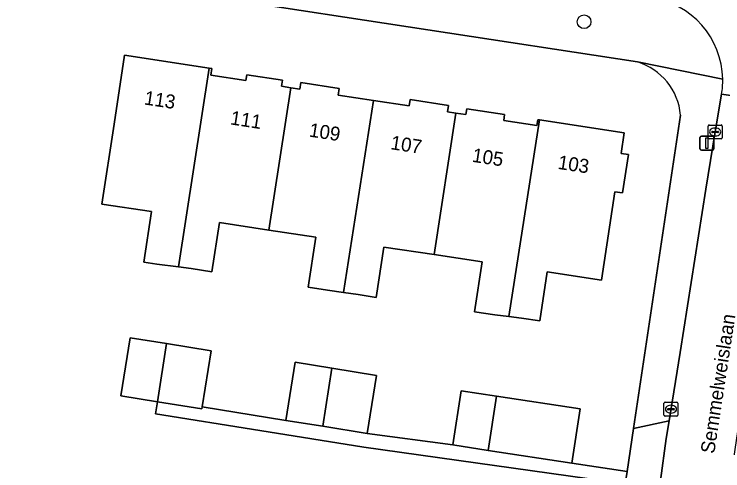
# Model space of a CAD drawing. Extents: x 161483 to 162250, y 379484 to 380833.
# Drawn here: x 161701.8 to 161752.7, y 380536.5 to 380569.3 of the extents above; entities that cross this region are included whole.
import ezdxf

# ---------------------------------------------------------------- set-up
doc = ezdxf.new("R2010")
doc.units = 0
for name, color, linetype in [('IMGEO_Boom', 7, 'Continuous'), ('IMGEO_Erf', 7, 'Continuous'), ('IMGEO_Kolk', 7, 'Continuous'), ('IMGEO_Lichtmast', 7, 'Continuous'), ('IMGEO_Openbare_ruimte_label', 7, 'Continuous'), ('IMGEO_Pand', 7, 'Continuous'), ('IMGEO_Pand_nummerreeks', 7, 'Continuous'), ('IMGEO_Rijbaan_lokaal_open', 7, 'Continuous'), ('IMGEO_Voetpad_open', 7, 'Continuous')]:
    doc.layers.add(name, color=color, linetype=linetype)

msp = doc.modelspace()

# ---------------------------------------------------------------- linework, layer by layer
at = {"layer": 'IMGEO_Boom'}
msp.add_circle((161742.75, 380568.781), 0.489, dxfattribs=at)
at = {"layer": 'IMGEO_Erf'}
for points in [[(161746.578, 380565.893), (161701.408, 380572.822), (161675.834, 380576.755), (161672.785, 380556.708), (161672.018, 380551.67), (161669.47, 380534.918), (161668.107, 380525.958), (161665.107, 380506.236), (161664.729, 380506.368), (161663.777, 380500), (161663.405, 380497.51), (161661.323, 380483.575), (161659.867, 380473.831), (161659.847, 380473.707), (161657.766, 380460.798), (161657.736, 380460.494), (161657.919, 380460.405), (161659.307, 380459.731), (161660.495, 380459.537), (161723.59, 380449.899)], [(161745.697, 380535.59), (161726.943, 380538.221), (161719.463, 380539.413), (161711.977, 380540.616), (161712.117, 380541.489), (161709.474, 380541.915), (161710.145, 380546.084), (161712.764, 380545.662), (161715.972, 380545.145), (161715.324, 380541.118), (161721.344, 380540.149), (161722.015, 380544.318), (161724.634, 380543.896), (161727.842, 380543.379), (161727.171, 380539.211), (161733.33, 380538.38), (161733.924, 380542.276), (161736.467, 380541.888), (161742.466, 380540.974), (161741.873, 380537.079), (161745.831, 380536.484), (161746.294, 380539.566), (161749.677, 380562.081)]]:
    msp.add_lwpolyline(points, dxfattribs=at)
msp.add_lwpolyline([(161726.524, 380549.18), (161725.478, 380549.329), (161724.318, 380549.495), (161722.932, 380549.706), (161723.479, 380553.305), (161720.102, 380553.819), (161716.562, 380554.357), (161716.025, 380550.83), (161714.543, 380551.056), (161713.62, 380551.174), (161712.06, 380551.374), (161711.14, 380551.514), (161711.692, 380555.142), (161708.127, 380555.685), (161709.001, 380561.429), (161709.753, 380566.372), (161715.834, 380565.447), (161716.02, 380565.419), (161715.947, 380564.943), (161718.465, 380564.56), (161718.529, 380564.98), (161721.095, 380564.59), (161721.028, 380564.146), (161721.688, 380564.045), (161722.334, 380563.947), (161722.405, 380564.413), (161725.167, 380563.992), (161725.095, 380563.517), (161727.619, 380563.133), (161730.181, 380562.743), (161730.249, 380563.195), (161733.007, 380562.775), (161732.936, 380562.313), (161733.549, 380562.22), (161734.264, 380562.111), (161734.329, 380562.538), (161737.044, 380562.124), (161736.977, 380561.685), (161739.367, 380561.321), (161739.432, 380561.749), (161739.545, 380561.732), (161745.625, 380560.807), (161745.4, 380559.327), (161745.935, 380559.246), (161745.516, 380556.491), (161744.959, 380556.576), (161743.991, 380550.215), (161740.106, 380550.807), (161739.572, 380547.299), (161738.251, 380547.5), (161737.353, 380547.604), (161736.35, 380547.72), (161734.887, 380547.943), (161735.433, 380551.528), (161731.972, 380552.055), (161728.374, 380552.602), (161727.823, 380548.983)], close=True, dxfattribs=at)
msp.add_arc((161745.279, 380561.671), 4.417, 5.3231, 72.8963, dxfattribs=at)
at = {"layer": 'IMGEO_Kolk'}
for p, q in [((161751.659, 380560.44), (161751.659, 380561.292)), ((161751.734, 380561.366), (161752.586, 380561.366)), ((161752.147, 380561.146), (161752.172, 380561.146)), ((161752.66, 380561.292), (161752.66, 380560.44)), ((161751.918, 380560.86), (161751.918, 380560.872)), ((161752.356, 380560.823), (161751.958, 380560.823)), ((161751.961, 380560.909), (161752.359, 380560.909)), ((161752.402, 380560.872), (161752.402, 380560.86)), ((161752.586, 380560.366), (161751.734, 380560.366)), ((161752.17, 380560.586), (161752.145, 380560.586)), ((161748.486, 380540.524), (161748.486, 380541.376)), ((161748.561, 380541.45), (161749.413, 380541.45)), ((161749.487, 380541.376), (161749.487, 380540.524)), ((161748.745, 380540.944), (161748.745, 380540.956)), ((161749.183, 380540.907), (161748.785, 380540.907)), ((161748.788, 380540.993), (161749.186, 380540.993)), ((161748.974, 380541.23), (161748.999, 380541.23)), ((161749.229, 380540.956), (161749.229, 380540.944)), ((161749.413, 380540.45), (161748.561, 380540.45)), ((161748.997, 380540.67), (161748.972, 380540.67))]:
    msp.add_line(p, q, dxfattribs=at)
for points in [[(161751.659, 380560.44), (161751.659, 380561.292)], [(161751.734, 380561.366), (161752.586, 380561.366)], [(161752.66, 380561.292), (161752.66, 380560.44)], [(161752.586, 380560.366), (161751.734, 380560.366)], [(161748.486, 380540.524), (161748.486, 380541.376)], [(161748.561, 380541.45), (161749.413, 380541.45)], [(161749.487, 380541.376), (161749.487, 380540.524)], [(161749.413, 380540.45), (161748.561, 380540.45)]]:
    msp.add_lwpolyline(points, dxfattribs=at)
for centre, radius, start, end in [((161751.736, 380561.29), 0.0765, 91.552, 178.448), ((161751.736, 380561.29), 0.0765, 91.552, 178.448), ((161752.584, 380561.29), 0.0765, 1.552, 88.448), ((161752.584, 380561.29), 0.0765, 1.552, 88.448), ((161751.958, 380560.869), 0.0403, 85.8775, 175.7526), ((161751.955, 380560.859), 0.0366, 178.938, 274.7102), ((161752.359, 380560.866), 0.043, 264.8664, 352.4533), ((161752.363, 380560.871), 0.0386, 1.7309, 96.639), ((161751.736, 380560.442), 0.0765, 181.552, 268.448), ((161751.736, 380560.442), 0.0765, 181.552, 268.448), ((161752.584, 380560.442), 0.0765, 271.552, 358.448), ((161752.584, 380560.442), 0.0765, 271.552, 358.448), ((161748.563, 380541.374), 0.0765, 91.552, 178.448), ((161748.563, 380541.374), 0.0765, 91.552, 178.448), ((161749.411, 380541.374), 0.0765, 1.552, 88.448), ((161749.411, 380541.374), 0.0765, 1.552, 88.448), ((161748.785, 380540.953), 0.0403, 85.8775, 175.7526), ((161748.782, 380540.943), 0.0366, 178.938, 274.7102), ((161749.186, 380540.95), 0.043, 264.8664, 352.4533), ((161749.19, 380540.955), 0.0386, 1.7309, 96.639), ((161748.563, 380540.526), 0.0765, 181.552, 268.448), ((161748.563, 380540.526), 0.0765, 181.552, 268.448), ((161749.411, 380540.526), 0.0765, 271.552, 358.448), ((161749.411, 380540.526), 0.0765, 271.552, 358.448)]:
    msp.add_arc(centre, radius, start, end, dxfattribs=at)
for centre, major_axis, ratio, start_param, end_param in [((161752.146, 380560.866), (-0.387, 0.002), 0.722429, 4.712389, 7.853982), ((161752.171, 380560.866), (-0.39, 0.002), 0.717154, 1.570796, 4.712389), ((161748.973, 380540.95), (-0.387, 0.002), 0.722429, 4.712389, 7.853982), ((161748.998, 380540.95), (-0.39, 0.002), 0.717154, 1.570796, 4.712389)]:
    msp.add_ellipse(centre, major_axis=major_axis, ratio=ratio, start_param=start_param, end_param=end_param, dxfattribs=at)
at = {"layer": 'IMGEO_Lichtmast'}
for p, q in [((161751.068, 380559.66), (161751.068, 380560.46)), ((161751.068, 380560.46), (161751.068, 380559.66)), ((161751.168, 380560.56), (161751.958, 380560.56)), ((161751.958, 380560.56), (161751.168, 380560.56)), ((161752.058, 380560.46), (161752.058, 380559.66)), ((161752.058, 380559.66), (161752.058, 380560.46)), ((161751.958, 380559.56), (161751.168, 380559.56)), ((161751.168, 380559.56), (161751.958, 380559.56))]:
    msp.add_line(p, q, dxfattribs=at)
msp.add_lwpolyline([(161751.488, 380560.435), (161751.638, 380560.435), (161751.638, 380559.685), (161751.488, 380559.685), (161751.488, 380560.435)], dxfattribs=at)
for centre, start, end in [((161751.168, 380560.46), 90, 180), ((161751.168, 380560.46), 90, 180), ((161751.958, 380560.46), 0, 90), ((161751.958, 380560.46), 360, 90), ((161751.168, 380559.66), 180, 270), ((161751.168, 380559.66), 180, 270), ((161751.958, 380559.66), 270, 0), ((161751.958, 380559.66), 270, 0)]:
    msp.add_arc(centre, 0.1, start, end, dxfattribs=at)
at = {"layer": 'IMGEO_Pand'}
for points in [[(161713.62, 380551.174), (161715.834, 380565.447), (161709.753, 380566.372), (161709.001, 380561.429), (161708.127, 380555.685), (161711.692, 380555.142), (161711.14, 380551.514), (161712.06, 380551.374)], [(161714.543, 380551.056), (161716.025, 380550.83), (161716.562, 380554.357), (161720.102, 380553.819), (161721.688, 380564.045), (161721.028, 380564.146), (161721.095, 380564.59), (161718.529, 380564.98), (161718.465, 380564.56), (161715.947, 380564.943), (161716.02, 380565.419), (161715.834, 380565.447), (161713.62, 380551.174)], [(161725.478, 380549.329), (161727.619, 380563.133), (161725.095, 380563.517), (161725.167, 380563.992), (161722.405, 380564.413), (161722.334, 380563.947), (161721.688, 380564.045), (161720.102, 380553.819), (161723.479, 380553.305), (161722.932, 380549.706), (161724.318, 380549.495)], [(161726.524, 380549.18), (161727.823, 380548.983), (161728.374, 380552.602), (161731.972, 380552.055), (161733.549, 380562.22), (161732.936, 380562.313), (161733.007, 380562.775), (161730.249, 380563.195), (161730.181, 380562.743), (161727.619, 380563.133), (161725.478, 380549.329)], [(161737.353, 380547.604), (161739.545, 380561.732), (161739.432, 380561.749), (161739.367, 380561.321), (161736.977, 380561.685), (161737.044, 380562.124), (161734.329, 380562.538), (161734.264, 380562.111), (161733.549, 380562.22), (161731.972, 380552.055), (161735.433, 380551.528), (161734.887, 380547.943), (161736.35, 380547.72)], [(161738.251, 380547.5), (161739.572, 380547.299), (161740.106, 380550.807), (161743.991, 380550.215), (161744.959, 380556.576), (161745.516, 380556.491), (161745.935, 380559.246), (161745.4, 380559.327), (161745.625, 380560.807), (161739.545, 380561.732), (161737.353, 380547.604)], [(161712.764, 380545.662), (161710.145, 380546.084), (161709.474, 380541.915), (161712.117, 380541.489)], [(161715.972, 380545.145), (161712.764, 380545.662), (161712.117, 380541.489), (161715.301, 380540.977), (161715.324, 380541.118)], [(161724.634, 380543.896), (161722.015, 380544.318), (161721.344, 380540.149), (161723.987, 380539.723)], [(161724.634, 380543.896), (161723.987, 380539.723), (161727.171, 380539.211), (161727.842, 380543.379)], [(161735.863, 380537.994), (161736.467, 380541.888), (161733.924, 380542.276), (161733.33, 380538.38)], [(161735.863, 380537.994), (161741.873, 380537.079), (161742.466, 380540.974), (161736.467, 380541.888)]]:
    msp.add_lwpolyline(points, close=True, dxfattribs=at)
at = {"layer": 'IMGEO_Rijbaan_lokaal_open'}
for points in [[(161753.363, 380536.499), (161753.467, 380537.247), (161753.9, 380540.172), (161755.535, 380550.773), (161757.034, 380560.392), (161757.402, 380562.904), (161752.625, 380563.589), (161752.161, 380560.866), (161751.484, 380556.751), (161749.641, 380545.022), (161748.852, 380540.104), (161748.652, 380538.854), (161748.238, 380535.839), (161748.011, 380534.961), (161747.898, 380534.562), (161747.662, 380533.825)], [(161752.625, 380563.589), (161757.402, 380562.904)]]:
    msp.add_lwpolyline(points, dxfattribs=at)
for centre, radius, start, end in [((161746.694, 380564.557), 6.009, 0.8814, 82.0228), ((161746.704, 380564.552), 5.999, 350.7631, 0.9274)]:
    msp.add_arc(centre, radius, start, end, dxfattribs=at)
at = {"layer": 'IMGEO_Voetpad_open'}
for points in [[(161676.405, 380581.019), (161675.834, 380576.755), (161701.408, 380572.822), (161746.578, 380565.893), (161752.702, 380564.649)], [(161752.702, 380564.649), (161746.578, 380565.893)], [(161749.677, 380562.081), (161746.294, 380539.566), (161748.852, 380540.104), (161749.641, 380545.022), (161751.484, 380556.751), (161752.161, 380560.866), (161752.625, 380563.589)], [(161748.238, 380535.839), (161748.652, 380538.854), (161748.852, 380540.104), (161746.294, 380539.566), (161745.831, 380536.484), (161745.697, 380535.59), (161745.623, 380535.1), (161745.182, 380533.675), (161744.227, 380532.481), (161745.615, 380530.377), (161746.474, 380531.506)]]:
    msp.add_lwpolyline(points, dxfattribs=at)
msp.add_lwpolyline([(161727.171, 380539.211), (161723.987, 380539.723), (161721.344, 380540.149), (161715.324, 380541.118), (161715.301, 380540.977), (161712.117, 380541.489), (161711.977, 380540.616), (161719.463, 380539.413), (161726.943, 380538.221), (161745.697, 380535.59), (161745.831, 380536.484), (161741.873, 380537.079), (161735.863, 380537.994), (161733.33, 380538.38)], close=True, dxfattribs=at)
for centre, radius, start, end in [((161746.694, 380564.557), 6.009, 0.8814, 82.0228), ((161745.279, 380561.671), 4.417, 5.3231, 72.8963), ((161746.704, 380564.552), 5.999, 350.7631, 0.9274)]:
    msp.add_arc(centre, radius, start, end, dxfattribs=at)

# ---------------------------------------------------------------- texts
at = {"layer": 'IMGEO_Openbare_ruimte_label'}
msp.add_text('Semmelweislaan', height=1, rotation=81.3105, dxfattribs=at).set_placement((161752.094, 380537.718))
at = {"layer": 'IMGEO_Pand_nummerreeks'}
for s, rotation, p in [('113', 351.3535, (161711.118, 380562.847)), ('111', 351.2086, (161717.303, 380561.414)), ('109', 351.2086, (161722.955, 380560.54)), ('107', 351.2086, (161728.81, 380559.634)), ('105', 351.2086, (161734.665, 380558.729)), ('103', 351.3512, (161740.819, 380558.22))]:
    msp.add_text(s, height=1, rotation=rotation, dxfattribs=at).set_placement(p)

doc.saveas('drawing.dxf')
